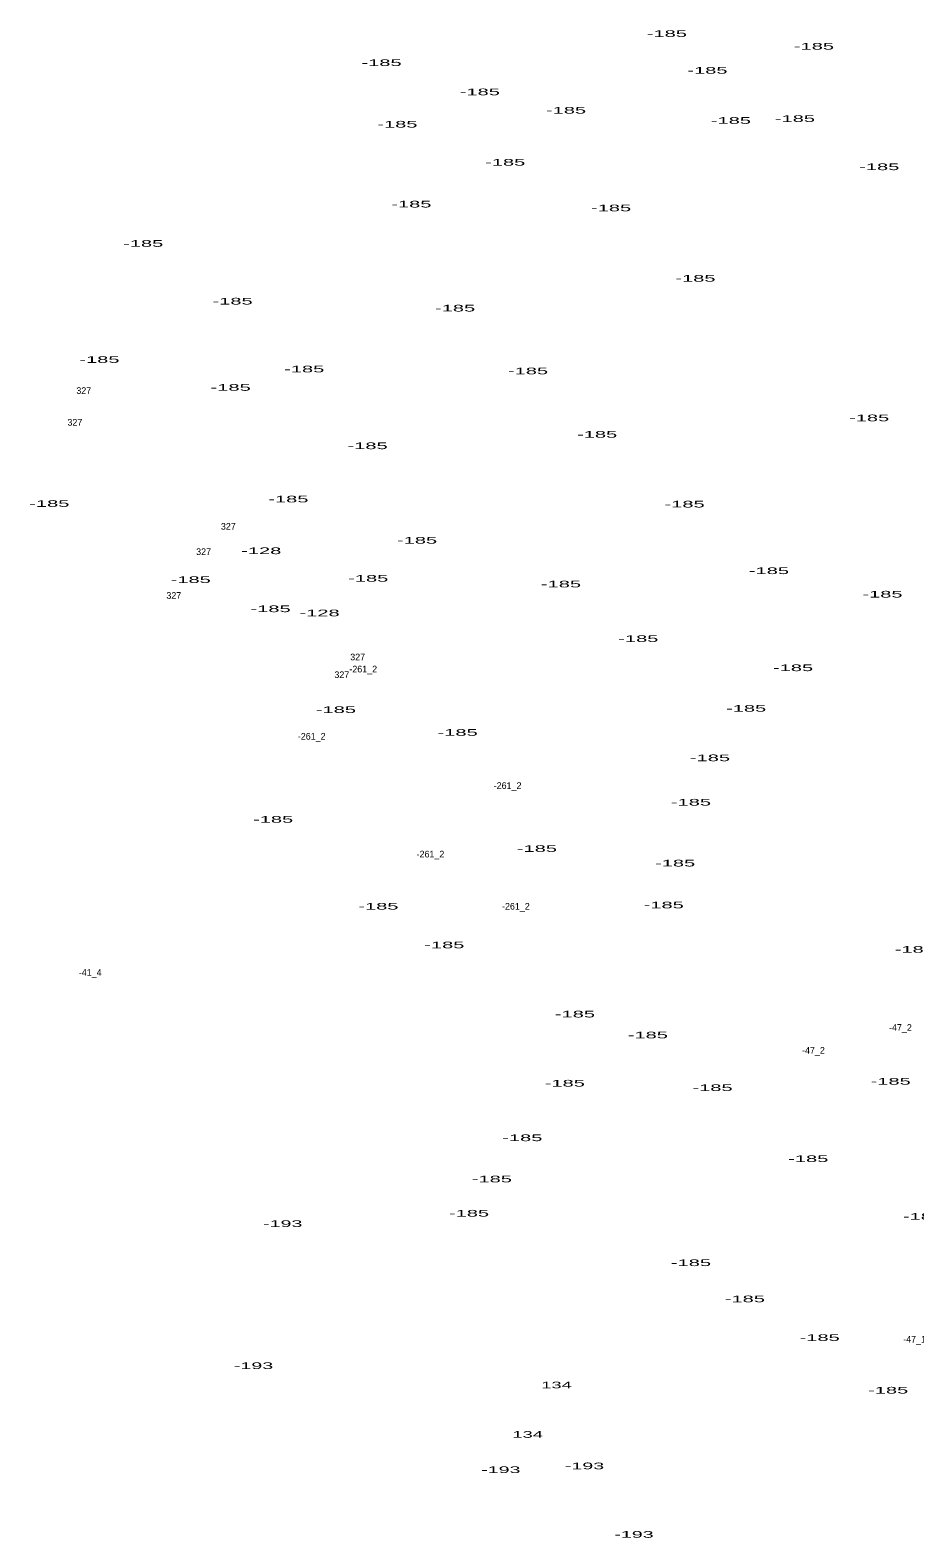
# Model space of a CAD drawing. Extents: x -658595 to -655205, y -1004347 to -1000147.
# Drawn here: x -657992 to -657461, y -1002227 to -1001323 of the extents above; entities that cross this region are included whole.
import ezdxf
from ezdxf.enums import TextEntityAlignment as Align

# ---------------------------------------------------------------- set-up
doc = ezdxf.new("R2010")
doc.units = 0
doc.header["$LTSCALE"] = 1.6
doc.layers.add('24', color=7, linetype='Continuous')

msp = doc.modelspace()

# ---------------------------------------------------------------- texts
at = {"layer": '24'}
for s, width, p in [('-185', 2.25, (-657609.591, -1001327.03)), ('-185', 2.25, (-657521.351, -1001334.64)), ('-185', 2.25, (-657780.761, -1001344.5)), ('-185', 2.25, (-657585.251, -1001349.1)), ('-185', 2.25, (-657721.811, -1001362.01)), ('-185', 2.25, (-657670.081, -1001373.04)), ('-185', 2.25, (-657532.761, -1001378.02)), ('-185', 2.25, (-657771.251, -1001381.41)), ('-185', 2.25, (-657571.171, -1001379.16)), ('-185', 2.25, (-657706.581, -1001404.24)), ('-185', 2.25, (-657482.171, -1001406.94)), ('-185', 2.25, (-657762.871, -1001429.35)), ('-185', 2.25, (-657643.061, -1001431.63)), ('-185', 2.25, (-657923.761, -1001452.94)), ('-185', 2.25, (-657592.471, -1001473.87)), ('-185', 2.25, (-657870.131, -1001487.57)), ('-185', 2.25, (-657736.631, -1001491.75)), ('-185', 2.25, (-657950.011, -1001522.57)), ('-185', 2.25, (-657827.151, -1001528.28)), ('-185', 2.25, (-657692.881, -1001529.42)), ('-185', 2.25, (-657871.271, -1001539.31)), ('-185', 2.25, (-657488.251, -1001557.58)), ('-185', 2.25, (-657651.431, -1001567.47)), ('-185', 2.25, (-657789.121, -1001574.32)), ('-185', 2.25, (-657980.061, -1001608.95)), ('-185', 2.25, (-657836.661, -1001606.28)), ('-185', 2.25, (-657598.941, -1001609.33)), ('-185', 2.25, (-657759.451, -1001631.02)), ('-128', 2.25, (-657852.931, -1001637.3)), ('-185', 2.25, (-657548.351, -1001649.28)), ('-185', 2.25, (-657895.241, -1001654.61)), ('-185', 2.25, (-657788.741, -1001653.84)), ('-185', 2.25, (-657673.111, -1001657.27)), ('-185', 2.25, (-657480.261, -1001663.36)), ('-185', 2.25, (-657847.311, -1001672.11)), ('-128', 2.25, (-657817.941, -1001674.59)), ('-185', 2.25, (-657626.711, -1001690)), ('-185', 2.25, (-657533.891, -1001707.49)), ('-185', 2.25, (-657808.131, -1001732.61)), ('-185', 2.25, (-657562.041, -1001731.84)), ('-185', 2.25, (-657735.101, -1001746.31)), ('-185', 2.25, (-657583.721, -1001761.52)), ('-185', 2.25, (-657595.131, -1001788.16)), ('-185', 2.25, (-657845.801, -1001798.44)), ('-185', 2.25, (-657687.561, -1001815.94)), ('-185', 2.25, (-657604.641, -1001824.69)), ('-185', 2.25, (-657782.651, -1001850.57)), ('-185', 2.25, (-657611.481, -1001849.8)), ('-185', 2.25, (-657743.091, -1001873.78)), ('-185', 2.25, (-657460.861, -1001876.44)), ('-185', 2.25, (-657664.741, -1001915.26)), ('-185', 2.25, (-657621.001, -1001927.81)), ('-185', 2.25, (-657670.821, -1001956.73)), ('-185', 2.25, (-657475.321, -1001955.59)), ('-185', 2.25, (-657582.201, -1001959.4)), ('-185', 2.25, (-657696.311, -1001989.46)), ('-185', 2.25, (-657524.761, -1002002.01)), ('-185', 2.25, (-657714.571, -1002014.19)), ('-185', 2.25, (-657728.261, -1002034.73)), ('-185', 2.25, (-657455.921, -1002036.64)), ('-193', 2.2, (-657840.045, -1002040.95)), ('-185', 2.25, (-657595.131, -1002064.42)), ('-185', 2.25, (-657562.801, -1002086.11)), ('-185', 2.25, (-657517.911, -1002109.32)), ('-193', 2.2, (-657857.545, -1002126.18)), ('134', 2.05, (-657675.793, -1002137.76)), ('-185', 2.25, (-657476.831, -1002140.9)), ('134', 2.05, (-657693.103, -1002167.44)), ('-193', 2.2, (-657709.205, -1002188.58)), ('-193', 2.2, (-657658.995, -1002186.3)), ('-193', 2.2, (-657629.325, -1002227.4))]:
    msp.add_text(s, height=4, dxfattribs=dict(at, width=width)).set_placement(p, align=Align.CENTER)
for s, p in [('327', (-657959.403, -1001541.2)), ('327', (-657964.733, -1001560.23)), ('327', (-657872.683, -1001622.63)), ('327', (-657887.513, -1001637.85)), ('327', (-657905.393, -1001664.1)), ('327', (-657795.093, -1001701.01)), ('327', (-657804.603, -1001711.66)), ('-261_2', (-657791.752, -1001708.26)), ('-261_2', (-657822.662, -1001748.6)), ('-261_2', (-657705.152, -1001778.17)), ('-261_2', (-657751.432, -1001819.28)), ('-261_2', (-657700.162, -1001850.59)), ('-41_4', (-657955.555, -1001890.29)), ('-47_2', (-657469.482, -1001923.29)), ('-47_2', (-657521.652, -1001937)), ('-47_1', (-657460.996, -1002110.33))]:
    msp.add_text(s, height=4, dxfattribs=at).set_placement(p, align=Align.CENTER)

doc.saveas('drawing.dxf')
